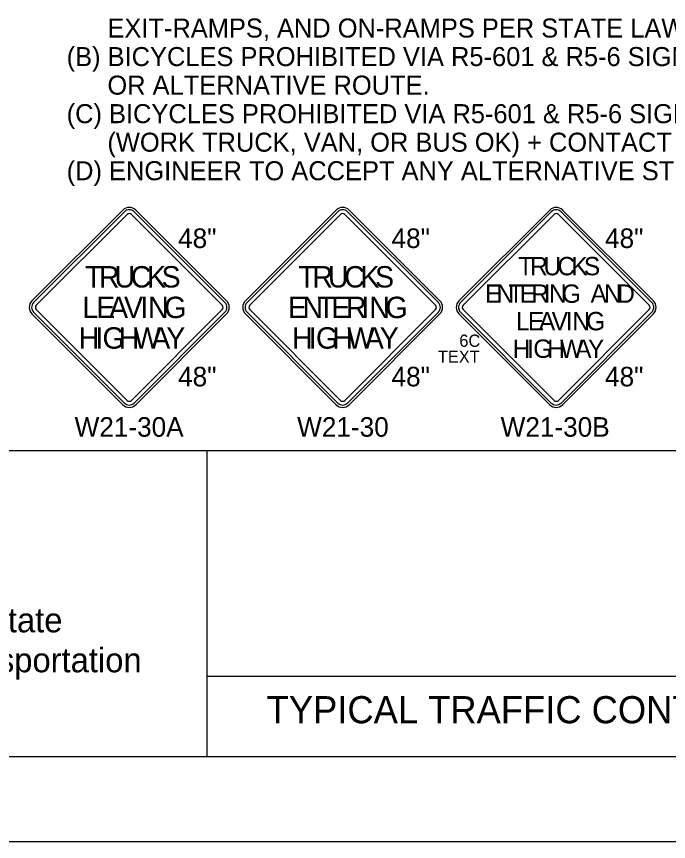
# Model space of a CAD drawing. Extents: x 99999 to 100116, y 99995 to 100013.
# Drawn here: x 100011.504 to 100013.904, y 99999.687 to 100002.723 of the extents above; entities that cross this region are included whole.
import ezdxf

# ---------------------------------------------------------------- set-up
doc = ezdxf.new("R2010")
doc.units = 0
for name, color, linetype in [('SH_GI_GeneralNotesBodyText', 7, 'Continuous'), ('SH_GI_PlotLimits', 7, 'Continuous'), ('SH_GI_SheetBorder', 7, 'Continuous'), ('SH_GI_SheetTextInCells', 7, 'Continuous'), ('SH_GI_TitleBlockText', 7, 'Continuous'), ('TR_SN_ConstructionSigns', 7, 'Continuous')]:
    doc.layers.add(name, color=color, linetype=linetype)

msp = doc.modelspace()

# ---------------------------------------------------------------- linework, layer by layer
at = {"layer": 'SH_GI_PlotLimits'}
msp.add_lwpolyline([(99999.0625, 99999.6875), (100016.0625, 99999.6875), (100016.0625, 100010.6875), (99999.0625, 100010.6875)], close=True, dxfattribs=at)
at = {"layer": 'SH_GI_SheetBorder'}
for p, q in [((100000, 100001.1259), (100015.75, 100001.1259)), ((100012.2055, 100001.1259), (100012.2055, 100000)), ((100012.2055, 100000.2955), (100015.2079, 100000.2955)), ((100000, 100000), (100015.75, 100000))]:
    msp.add_line(p, q, dxfattribs=at)
at = {"layer": 'TR_SN_ConstructionSigns'}
for p, q in [((100011.8955, 100002.0107), (100011.5613, 100001.6766)), ((100011.9014, 100002.0048), (100011.5673, 100001.6707)), ((100012.2713, 100001.6707), (100011.9372, 100002.0048)), ((100012.2773, 100001.6766), (100011.9432, 100002.0107)), ((100012.6812, 100002.0107), (100012.3471, 100001.6766)), ((100012.6871, 100002.0048), (100012.353, 100001.6707)), ((100013.057, 100001.6707), (100012.7229, 100002.0048)), ((100013.063, 100001.6766), (100012.7289, 100002.0107)), ((100013.4669, 100002.0107), (100013.1328, 100001.6766)), ((100013.4729, 100002.0048), (100013.1387, 100001.6707)), ((100013.8428, 100001.6707), (100013.5087, 100002.0048)), ((100013.8487, 100001.6766), (100013.5146, 100002.0107)), ((100011.5773, 100001.6607), (100011.9114, 100001.9948)), ((100011.9273, 100001.9948), (100012.2614, 100001.6607)), ((100012.363, 100001.6607), (100012.6971, 100001.9948)), ((100012.713, 100001.9948), (100013.0471, 100001.6607)), ((100013.1487, 100001.6607), (100013.4828, 100001.9948)), ((100013.4987, 100001.9948), (100013.8328, 100001.6607)), ((100011.9114, 100001.3107), (100011.5773, 100001.6448)), ((100012.2614, 100001.6448), (100011.9273, 100001.3107)), ((100012.6971, 100001.3107), (100012.363, 100001.6448)), ((100013.0471, 100001.6448), (100012.713, 100001.3107)), ((100013.4828, 100001.3107), (100013.1487, 100001.6448)), ((100013.8328, 100001.6448), (100013.4987, 100001.3107)), ((100011.5613, 100001.6289), (100011.8955, 100001.2948)), ((100011.5673, 100001.6349), (100011.9014, 100001.3008)), ((100011.9372, 100001.3008), (100012.2713, 100001.6349)), ((100011.9432, 100001.2948), (100012.2773, 100001.6289)), ((100012.3471, 100001.6289), (100012.6812, 100001.2948)), ((100012.353, 100001.6349), (100012.6871, 100001.3008)), ((100012.7229, 100001.3008), (100013.057, 100001.6349)), ((100012.7289, 100001.2948), (100013.063, 100001.6289)), ((100013.1328, 100001.6289), (100013.4669, 100001.2948)), ((100013.1387, 100001.6349), (100013.4729, 100001.3008)), ((100013.5087, 100001.3008), (100013.8428, 100001.6349)), ((100013.5146, 100001.2948), (100013.8487, 100001.6289))]:
    msp.add_line(p, q, dxfattribs=at)
for centre, radius, start, end in [((100011.9193, 100001.9869), 0.0338, 45, 135), ((100011.9193, 100001.9869), 0.0253, 45, 135), ((100012.705, 100001.9869), 0.0338, 45, 135), ((100012.705, 100001.9869), 0.0253, 45, 135), ((100013.4908, 100001.9869), 0.0338, 45, 135), ((100013.4908, 100001.9869), 0.0253, 45, 135), ((100011.9193, 100001.9869), 0.0113, 45, 135), ((100012.705, 100001.9869), 0.0113, 45, 135), ((100013.4908, 100001.9869), 0.0113, 45, 135), ((100011.5852, 100001.6528), 0.0338, 135, 225), ((100011.5852, 100001.6528), 0.0253, 135, 225), ((100012.2534, 100001.6528), 0.0253, 315, 45), ((100012.2534, 100001.6528), 0.0338, 315, 45), ((100012.3709, 100001.6528), 0.0338, 135, 225), ((100012.3709, 100001.6528), 0.0253, 135, 225), ((100013.0391, 100001.6528), 0.0253, 315, 45), ((100013.0391, 100001.6528), 0.0338, 315, 45), ((100013.1566, 100001.6528), 0.0338, 135, 225), ((100013.1566, 100001.6528), 0.0253, 135, 225), ((100013.8249, 100001.6528), 0.0253, 315, 45), ((100013.8249, 100001.6528), 0.0338, 315, 45), ((100011.5852, 100001.6528), 0.0113, 135, 225), ((100012.2534, 100001.6528), 0.0113, 315, 45), ((100012.3709, 100001.6528), 0.0113, 135, 225), ((100013.0391, 100001.6528), 0.0113, 315, 45), ((100013.1566, 100001.6528), 0.0113, 135, 225), ((100013.8249, 100001.6528), 0.0113, 315, 45), ((100011.9193, 100001.3187), 0.0113, 225, 315), ((100012.705, 100001.3187), 0.0113, 225, 315), ((100013.4908, 100001.3187), 0.0113, 225, 315), ((100011.9193, 100001.3187), 0.0338, 225, 315), ((100011.9193, 100001.3187), 0.0253, 225, 315), ((100012.705, 100001.3187), 0.0338, 225, 315), ((100012.705, 100001.3187), 0.0253, 225, 315), ((100013.4908, 100001.3187), 0.0338, 225, 315), ((100013.4908, 100001.3187), 0.0253, 225, 315)]:
    msp.add_arc(centre, radius, start, end, dxfattribs=at)

# ---------------------------------------------------------------- texts
at = {"layer": 'SH_GI_GeneralNotesBodyText'}
for s, p in [('EXIT-RAMPS, AND ON-RAMPS PER STATE LAW.', (100011.839, 100002.6456)), ('(B) BICYCLES PROHIBITED VIA R5-601 & R5-6 SIGNS. PROVIDE SIGNED DETOUR ', (100011.689, 100002.5406)), ('OR ALTERNATIVE ROUTE.', (100011.839, 100002.4356)), ('(C) BICYCLES PROHIBITED VIA R5-601 & R5-6 SIGNS. PROVIDE FREE SHUTTLE ', (100011.689, 100002.3306)), ('(WORK TRUCK, VAN, OR BUS OK) + CONTACT INFORMATION OR PHONE BOX.', (100011.839, 100002.2256)), ('(D) ENGINEER TO ACCEPT ANY ALTERNATIVE STRATEGIES.', (100011.689, 100002.1206))]:
    msp.add_text(s, height=0.07, rotation=360, dxfattribs=at).set_placement(p)
at = {"layer": 'SH_GI_SheetTextInCells'}
for s, p in [('Washington State', (100010.7229, 100000.4571)), ('Department of Transportation', (100010.3916, 100000.3101))]:
    msp.add_text(s, height=0.090072, dxfattribs=at).set_placement(p)
at = {"layer": 'SH_GI_TitleBlockText'}
msp.add_text('TYPICAL TRAFFIC CONTROL PLANS', height=0.1, dxfattribs=at).set_placement((100012.4251, 100000.1224))
at = {"layer": 'TR_SN_ConstructionSigns'}
for s, p in [('48"', (100012.0991, 100001.8713)), ('48"', (100012.8848, 100001.8713)), ('48"', (100013.6706, 100001.8713)), ('48"', (100012.0991, 100001.3622)), ('48"', (100012.8848, 100001.3622)), ('48"', (100013.6706, 100001.3622)), ('W21-30A', (100011.7182, 100001.1769)), ('W21-30', (100012.5373, 100001.1769)), ('W21-30B', (100013.2863, 100001.1769))]:
    msp.add_text(s, height=0.072, rotation=360, dxfattribs=at).set_placement(p)
for s, height, p in [('T', 0.0675, (100013.351, 100001.7709)), ('R', 0.0675, (100013.3949, 100001.7709)), ('U', 0.0675, (100013.4442, 100001.7709)), ('C', 0.0675, (100013.4955, 100001.7709)), ('K', 0.0675, (100013.5468, 100001.7709)), ('S', 0.0675, (100013.5927, 100001.7709)), ('T', 0.0787, (100011.7563, 100001.7259)), ('R', 0.0787, (100011.8075, 100001.7259)), ('U', 0.0787, (100011.865, 100001.7259)), ('C', 0.0787, (100011.9248, 100001.7259)), ('K', 0.0787, (100011.9847, 100001.7259)), ('S', 0.0787, (100012.0382, 100001.7259)), ('T', 0.0787, (100012.542, 100001.7259)), ('R', 0.0787, (100012.5932, 100001.7259)), ('U', 0.0787, (100012.6507, 100001.7259)), ('C', 0.0787, (100012.7106, 100001.7259)), ('K', 0.0787, (100012.7704, 100001.7259)), ('S', 0.0787, (100012.824, 100001.7259)), ('E', 0.0675, (100013.2286, 100001.6696)), ('N', 0.0675, (100013.271, 100001.6696)), ('T', 0.0675, (100013.3154, 100001.6696)), ('E', 0.0675, (100013.3565, 100001.6696)), ('R', 0.0675, (100013.3989, 100001.6696)), ('I', 0.0675, (100013.4448, 100001.6696)), ('N', 0.0675, (100013.4646, 100001.6696)), ('G', 0.0675, (100013.5118, 100001.6696)), ('A', 0.0675, (100013.6171, 100001.6696)), ('N', 0.0675, (100013.667, 100001.6696)), ('D', 0.0675, (100013.7152, 100001.6696)), ('L', 0.0787, (100011.7465, 100001.6134)), ('E', 0.0787, (100011.7977, 100001.6134)), ('A', 0.0787, (100011.8449, 100001.6134)), ('V', 0.0787, (100011.9, 100001.6134)), ('I', 0.0787, (100011.9599, 100001.6134)), ('N', 0.0787, (100011.9882, 100001.6134)), ('G', 0.0787, (100012.0481, 100001.6134)), ('E', 0.0787, (100012.5034, 100001.6134)), ('N', 0.0787, (100012.557, 100001.6134)), ('T', 0.0787, (100012.6121, 100001.6134)), ('E', 0.0787, (100012.6633, 100001.6134)), ('R', 0.0787, (100012.7169, 100001.6134)), ('I', 0.0787, (100012.7743, 100001.6134)), ('N', 0.0787, (100012.8027, 100001.6134)), ('G', 0.0787, (100012.8625, 100001.6134)), ('L', 0.0675, (100013.3426, 100001.5684)), ('E', 0.0675, (100013.3865, 100001.5684)), ('A', 0.0675, (100013.427, 100001.5684)), ('V', 0.0675, (100013.4742, 100001.5684)), ('I', 0.0675, (100013.5255, 100001.5684)), ('N', 0.0675, (100013.5498, 100001.5684)), ('G', 0.0675, (100013.6011, 100001.5684)), ('H', 0.0787, (100011.7327, 100001.5009)), ('I', 0.0787, (100011.7941, 100001.5009)), ('G', 0.0787, (100011.8209, 100001.5009)), ('H', 0.0787, (100011.8807, 100001.5009)), ('W', 0.0787, (100011.9359, 100001.5009)), ('A', 0.0787, (100012.0004, 100001.5009)), ('Y', 0.0787, (100012.0556, 100001.5009)), ('H', 0.0787, (100012.5184, 100001.5009)), ('I', 0.0787, (100012.5798, 100001.5009)), ('G', 0.0787, (100012.6066, 100001.5009)), ('H', 0.0787, (100012.6665, 100001.5009)), ('W', 0.0787, (100012.7216, 100001.5009)), ('A', 0.0787, (100012.7862, 100001.5009)), ('Y', 0.0787, (100012.8413, 100001.5009)), ('6C', 0.045, (100013.1343, 100001.5077)), ('H', 0.0675, (100013.3308, 100001.4671)), ('I', 0.0675, (100013.3834, 100001.4671)), ('G', 0.0675, (100013.4064, 100001.4671)), ('H', 0.0675, (100013.4577, 100001.4671)), ('W', 0.0675, (100013.5049, 100001.4671)), ('A', 0.0675, (100013.5603, 100001.4671)), ('Y', 0.0675, (100013.6075, 100001.4671)), ('TEXT', 0.045, (100013.0554, 100001.4491))]:
    msp.add_text(s, height=height, dxfattribs=at).set_placement(p)

doc.saveas('drawing.dxf')
